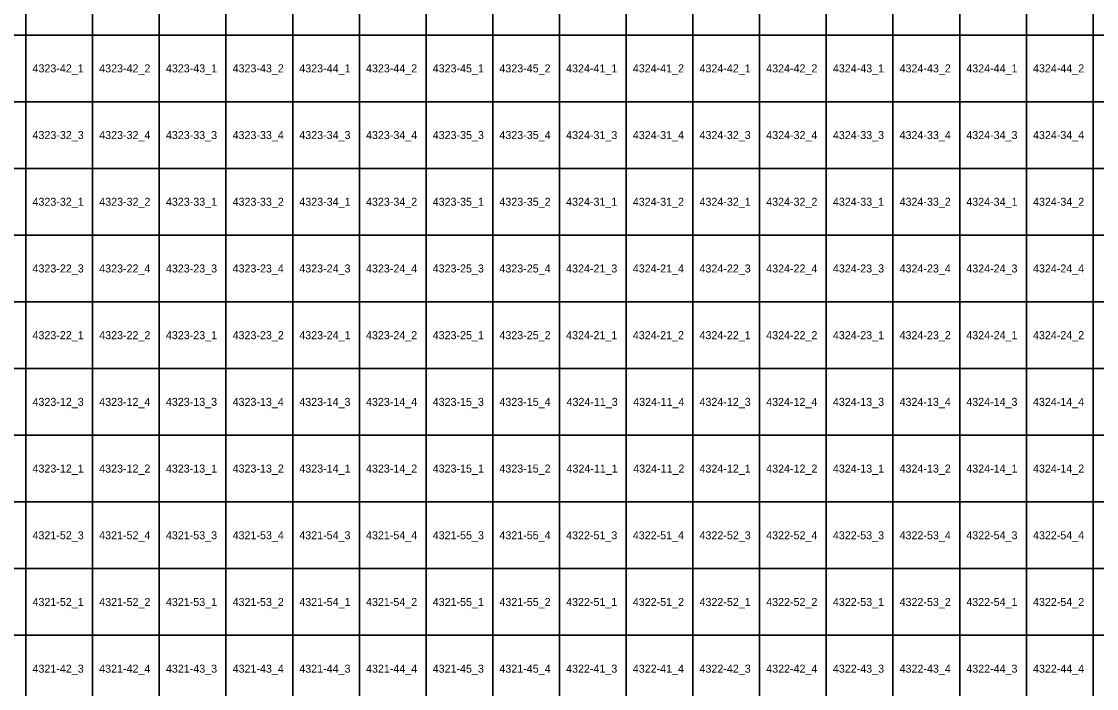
# Model space of a CAD drawing. Extents: x 312500 to 765000, y 172500 to 440000.
# Drawn here: x 554835 to 595129, y 318007 to 343007 of the extents above; entities that cross this region are included whole.
import ezdxf

# ---------------------------------------------------------------- set-up
doc = ezdxf.new("R2010")
doc.units = 0
doc.layers.add('Topo5_ramis_TKS2025', color=7, linetype='Continuous')
doc.layers.add('Topo5_ramis_TKS2025_Nr', color=7, linetype='Continuous')

msp = doc.modelspace()

# ---------------------------------------------------------------- linework, layer by layer
at = {"layer": 'Topo5_ramis_TKS2025'}
for points in [[(552500, 342500), (552500, 345000), (555000, 345000), (555000, 342500), (552500, 342500)], [(555000, 342500), (555000, 345000), (557500, 345000), (557500, 342500), (555000, 342500)], [(557500, 342500), (557500, 345000), (560000, 345000), (560000, 342500), (557500, 342500)], [(560000, 342500), (560000, 345000), (562500, 345000), (562500, 342500), (560000, 342500)], [(562500, 342500), (562500, 345000), (565000, 345000), (565000, 342500), (562500, 342500)], [(565000, 342500), (565000, 345000), (567500, 345000), (567500, 342500), (565000, 342500)], [(567500, 342500), (567500, 345000), (570000, 345000), (570000, 342500), (567500, 342500)], [(570000, 342500), (570000, 345000), (572500, 345000), (572500, 342500), (570000, 342500)], [(572500, 342500), (572500, 345000), (575000, 345000), (575000, 342500), (572500, 342500)], [(575000, 342500), (575000, 345000), (577500, 345000), (577500, 342500), (575000, 342500)], [(577500, 342500), (577500, 345000), (580000, 345000), (580000, 342500), (577500, 342500)], [(580000, 342500), (580000, 345000), (582500, 345000), (582500, 342500), (580000, 342500)], [(582500, 342500), (582500, 345000), (585000, 345000), (585000, 342500), (582500, 342500)], [(585000, 342500), (585000, 345000), (587500, 345000), (587500, 342500), (585000, 342500)], [(587500, 342500), (587500, 345000), (590000, 345000), (590000, 342500), (587500, 342500)], [(590000, 342500), (590000, 345000), (592500, 345000), (592500, 342500), (590000, 342500)], [(592500, 342500), (592500, 345000), (595000, 345000), (595000, 342500), (592500, 342500)], [(595000, 342500), (595000, 345000), (597500, 345000), (597500, 342500), (595000, 342500)], [(552500, 340000), (552500, 342500), (555000, 342500), (555000, 340000), (552500, 340000)], [(555000, 340000), (555000, 342500), (557500, 342500), (557500, 340000), (555000, 340000)], [(557500, 340000), (557500, 342500), (560000, 342500), (560000, 340000), (557500, 340000)], [(560000, 340000), (560000, 342500), (562500, 342500), (562500, 340000), (560000, 340000)], [(562500, 340000), (562500, 342500), (565000, 342500), (565000, 340000), (562500, 340000)], [(565000, 340000), (565000, 342500), (567500, 342500), (567500, 340000), (565000, 340000)], [(567500, 340000), (567500, 342500), (570000, 342500), (570000, 340000), (567500, 340000)], [(570000, 340000), (570000, 342500), (572500, 342500), (572500, 340000), (570000, 340000)], [(572500, 340000), (572500, 342500), (575000, 342500), (575000, 340000), (572500, 340000)], [(575000, 340000), (575000, 342500), (577500, 342500), (577500, 340000), (575000, 340000)], [(577500, 340000), (577500, 342500), (580000, 342500), (580000, 340000), (577500, 340000)], [(580000, 340000), (580000, 342500), (582500, 342500), (582500, 340000), (580000, 340000)], [(582500, 340000), (582500, 342500), (585000, 342500), (585000, 340000), (582500, 340000)], [(585000, 340000), (585000, 342500), (587500, 342500), (587500, 340000), (585000, 340000)], [(587500, 340000), (587500, 342500), (590000, 342500), (590000, 340000), (587500, 340000)], [(590000, 340000), (590000, 342500), (592500, 342500), (592500, 340000), (590000, 340000)], [(592500, 340000), (592500, 342500), (595000, 342500), (595000, 340000), (592500, 340000)], [(595000, 340000), (595000, 342500), (597500, 342500), (597500, 340000), (595000, 340000)], [(552500, 337500), (552500, 340000), (555000, 340000), (555000, 337500), (552500, 337500)], [(555000, 337500), (555000, 340000), (557500, 340000), (557500, 337500), (555000, 337500)], [(557500, 337500), (557500, 340000), (560000, 340000), (560000, 337500), (557500, 337500)], [(560000, 337500), (560000, 340000), (562500, 340000), (562500, 337500), (560000, 337500)], [(562500, 337500), (562500, 340000), (565000, 340000), (565000, 337500), (562500, 337500)], [(565000, 337500), (565000, 340000), (567500, 340000), (567500, 337500), (565000, 337500)], [(567500, 337500), (567500, 340000), (570000, 340000), (570000, 337500), (567500, 337500)], [(570000, 337500), (570000, 340000), (572500, 340000), (572500, 337500), (570000, 337500)], [(572500, 337500), (572500, 340000), (575000, 340000), (575000, 337500), (572500, 337500)], [(575000, 337500), (575000, 340000), (577500, 340000), (577500, 337500), (575000, 337500)], [(577500, 337500), (577500, 340000), (580000, 340000), (580000, 337500), (577500, 337500)], [(580000, 337500), (580000, 340000), (582500, 340000), (582500, 337500), (580000, 337500)], [(582500, 337500), (582500, 340000), (585000, 340000), (585000, 337500), (582500, 337500)], [(585000, 337500), (585000, 340000), (587500, 340000), (587500, 337500), (585000, 337500)], [(587500, 337500), (587500, 340000), (590000, 340000), (590000, 337500), (587500, 337500)], [(590000, 337500), (590000, 340000), (592500, 340000), (592500, 337500), (590000, 337500)], [(592500, 337500), (592500, 340000), (595000, 340000), (595000, 337500), (592500, 337500)], [(595000, 337500), (595000, 340000), (597500, 340000), (597500, 337500), (595000, 337500)], [(552500, 335000), (552500, 337500), (555000, 337500), (555000, 335000), (552500, 335000)], [(555000, 335000), (555000, 337500), (557500, 337500), (557500, 335000), (555000, 335000)], [(557500, 335000), (557500, 337500), (560000, 337500), (560000, 335000), (557500, 335000)], [(560000, 335000), (560000, 337500), (562500, 337500), (562500, 335000), (560000, 335000)], [(562500, 335000), (562500, 337500), (565000, 337500), (565000, 335000), (562500, 335000)], [(565000, 335000), (565000, 337500), (567500, 337500), (567500, 335000), (565000, 335000)], [(567500, 335000), (567500, 337500), (570000, 337500), (570000, 335000), (567500, 335000)], [(570000, 335000), (570000, 337500), (572500, 337500), (572500, 335000), (570000, 335000)], [(572500, 335000), (572500, 337500), (575000, 337500), (575000, 335000), (572500, 335000)], [(575000, 335000), (575000, 337500), (577500, 337500), (577500, 335000), (575000, 335000)], [(577500, 335000), (577500, 337500), (580000, 337500), (580000, 335000), (577500, 335000)], [(580000, 335000), (580000, 337500), (582500, 337500), (582500, 335000), (580000, 335000)], [(582500, 335000), (582500, 337500), (585000, 337500), (585000, 335000), (582500, 335000)], [(585000, 335000), (585000, 337500), (587500, 337500), (587500, 335000), (585000, 335000)], [(587500, 335000), (587500, 337500), (590000, 337500), (590000, 335000), (587500, 335000)], [(590000, 335000), (590000, 337500), (592500, 337500), (592500, 335000), (590000, 335000)], [(592500, 335000), (592500, 337500), (595000, 337500), (595000, 335000), (592500, 335000)], [(595000, 335000), (595000, 337500), (597500, 337500), (597500, 335000), (595000, 335000)], [(552500, 332500), (552500, 335000), (555000, 335000), (555000, 332500), (552500, 332500)], [(555000, 332500), (555000, 335000), (557500, 335000), (557500, 332500), (555000, 332500)], [(557500, 332500), (557500, 335000), (560000, 335000), (560000, 332500), (557500, 332500)], [(560000, 332500), (560000, 335000), (562500, 335000), (562500, 332500), (560000, 332500)], [(562500, 332500), (562500, 335000), (565000, 335000), (565000, 332500), (562500, 332500)], [(565000, 332500), (565000, 335000), (567500, 335000), (567500, 332500), (565000, 332500)], [(567500, 332500), (567500, 335000), (570000, 335000), (570000, 332500), (567500, 332500)], [(570000, 332500), (570000, 335000), (572500, 335000), (572500, 332500), (570000, 332500)], [(572500, 332500), (572500, 335000), (575000, 335000), (575000, 332500), (572500, 332500)], [(575000, 332500), (575000, 335000), (577500, 335000), (577500, 332500), (575000, 332500)], [(577500, 332500), (577500, 335000), (580000, 335000), (580000, 332500), (577500, 332500)], [(580000, 332500), (580000, 335000), (582500, 335000), (582500, 332500), (580000, 332500)], [(582500, 332500), (582500, 335000), (585000, 335000), (585000, 332500), (582500, 332500)], [(585000, 332500), (585000, 335000), (587500, 335000), (587500, 332500), (585000, 332500)], [(587500, 332500), (587500, 335000), (590000, 335000), (590000, 332500), (587500, 332500)], [(590000, 332500), (590000, 335000), (592500, 335000), (592500, 332500), (590000, 332500)], [(592500, 332500), (592500, 335000), (595000, 335000), (595000, 332500), (592500, 332500)], [(595000, 332500), (595000, 335000), (597500, 335000), (597500, 332500), (595000, 332500)], [(552500, 330000), (552500, 332500), (555000, 332500), (555000, 330000), (552500, 330000)], [(555000, 330000), (555000, 332500), (557500, 332500), (557500, 330000), (555000, 330000)], [(557500, 330000), (557500, 332500), (560000, 332500), (560000, 330000), (557500, 330000)], [(560000, 330000), (560000, 332500), (562500, 332500), (562500, 330000), (560000, 330000)], [(562500, 330000), (562500, 332500), (565000, 332500), (565000, 330000), (562500, 330000)], [(565000, 330000), (565000, 332500), (567500, 332500), (567500, 330000), (565000, 330000)], [(567500, 330000), (567500, 332500), (570000, 332500), (570000, 330000), (567500, 330000)], [(570000, 330000), (570000, 332500), (572500, 332500), (572500, 330000), (570000, 330000)], [(572500, 330000), (572500, 332500), (575000, 332500), (575000, 330000), (572500, 330000)], [(575000, 330000), (575000, 332500), (577500, 332500), (577500, 330000), (575000, 330000)], [(577500, 330000), (577500, 332500), (580000, 332500), (580000, 330000), (577500, 330000)], [(580000, 330000), (580000, 332500), (582500, 332500), (582500, 330000), (580000, 330000)], [(582500, 330000), (582500, 332500), (585000, 332500), (585000, 330000), (582500, 330000)], [(585000, 330000), (585000, 332500), (587500, 332500), (587500, 330000), (585000, 330000)], [(587500, 330000), (587500, 332500), (590000, 332500), (590000, 330000), (587500, 330000)], [(590000, 330000), (590000, 332500), (592500, 332500), (592500, 330000), (590000, 330000)], [(592500, 330000), (592500, 332500), (595000, 332500), (595000, 330000), (592500, 330000)], [(595000, 330000), (595000, 332500), (597500, 332500), (597500, 330000), (595000, 330000)], [(552500, 327500), (552500, 330000), (555000, 330000), (555000, 327500), (552500, 327500)], [(555000, 327500), (555000, 330000), (557500, 330000), (557500, 327500), (555000, 327500)], [(557500, 327500), (557500, 330000), (560000, 330000), (560000, 327500), (557500, 327500)], [(560000, 327500), (560000, 330000), (562500, 330000), (562500, 327500), (560000, 327500)], [(562500, 327500), (562500, 330000), (565000, 330000), (565000, 327500), (562500, 327500)], [(565000, 327500), (565000, 330000), (567500, 330000), (567500, 327500), (565000, 327500)], [(567500, 327500), (567500, 330000), (570000, 330000), (570000, 327500), (567500, 327500)], [(570000, 327500), (570000, 330000), (572500, 330000), (572500, 327500), (570000, 327500)], [(572500, 327500), (572500, 330000), (575000, 330000), (575000, 327500), (572500, 327500)], [(575000, 327500), (575000, 330000), (577500, 330000), (577500, 327500), (575000, 327500)], [(577500, 327500), (577500, 330000), (580000, 330000), (580000, 327500), (577500, 327500)], [(580000, 327500), (580000, 330000), (582500, 330000), (582500, 327500), (580000, 327500)], [(582500, 327500), (582500, 330000), (585000, 330000), (585000, 327500), (582500, 327500)], [(585000, 327500), (585000, 330000), (587500, 330000), (587500, 327500), (585000, 327500)], [(587500, 327500), (587500, 330000), (590000, 330000), (590000, 327500), (587500, 327500)], [(590000, 327500), (590000, 330000), (592500, 330000), (592500, 327500), (590000, 327500)], [(592500, 327500), (592500, 330000), (595000, 330000), (595000, 327500), (592500, 327500)], [(595000, 327500), (595000, 330000), (597500, 330000), (597500, 327500), (595000, 327500)], [(552500, 325000), (552500, 327500), (555000, 327500), (555000, 325000), (552500, 325000)], [(555000, 325000), (555000, 327500), (557500, 327500), (557500, 325000), (555000, 325000)], [(557500, 325000), (557500, 327500), (560000, 327500), (560000, 325000), (557500, 325000)], [(560000, 325000), (560000, 327500), (562500, 327500), (562500, 325000), (560000, 325000)], [(562500, 325000), (562500, 327500), (565000, 327500), (565000, 325000), (562500, 325000)], [(565000, 325000), (565000, 327500), (567500, 327500), (567500, 325000), (565000, 325000)], [(567500, 325000), (567500, 327500), (570000, 327500), (570000, 325000), (567500, 325000)], [(570000, 325000), (570000, 327500), (572500, 327500), (572500, 325000), (570000, 325000)], [(572500, 325000), (572500, 327500), (575000, 327500), (575000, 325000), (572500, 325000)], [(575000, 325000), (575000, 327500), (577500, 327500), (577500, 325000), (575000, 325000)], [(577500, 325000), (577500, 327500), (580000, 327500), (580000, 325000), (577500, 325000)], [(580000, 325000), (580000, 327500), (582500, 327500), (582500, 325000), (580000, 325000)], [(582500, 325000), (582500, 327500), (585000, 327500), (585000, 325000), (582500, 325000)], [(585000, 325000), (585000, 327500), (587500, 327500), (587500, 325000), (585000, 325000)], [(587500, 325000), (587500, 327500), (590000, 327500), (590000, 325000), (587500, 325000)], [(590000, 325000), (590000, 327500), (592500, 327500), (592500, 325000), (590000, 325000)], [(592500, 325000), (592500, 327500), (595000, 327500), (595000, 325000), (592500, 325000)], [(595000, 325000), (595000, 327500), (597500, 327500), (597500, 325000), (595000, 325000)], [(552500, 322500), (552500, 325000), (555000, 325000), (555000, 322500), (552500, 322500)], [(555000, 322500), (555000, 325000), (557500, 325000), (557500, 322500), (555000, 322500)], [(557500, 322500), (557500, 325000), (560000, 325000), (560000, 322500), (557500, 322500)], [(560000, 322500), (560000, 325000), (562500, 325000), (562500, 322500), (560000, 322500)], [(562500, 322500), (562500, 325000), (565000, 325000), (565000, 322500), (562500, 322500)], [(565000, 322500), (565000, 325000), (567500, 325000), (567500, 322500), (565000, 322500)], [(567500, 322500), (567500, 325000), (570000, 325000), (570000, 322500), (567500, 322500)], [(570000, 322500), (570000, 325000), (572500, 325000), (572500, 322500), (570000, 322500)], [(572500, 322500), (572500, 325000), (575000, 325000), (575000, 322500), (572500, 322500)], [(575000, 322500), (575000, 325000), (577500, 325000), (577500, 322500), (575000, 322500)], [(577500, 322500), (577500, 325000), (580000, 325000), (580000, 322500), (577500, 322500)], [(580000, 322500), (580000, 325000), (582500, 325000), (582500, 322500), (580000, 322500)], [(582500, 322500), (582500, 325000), (585000, 325000), (585000, 322500), (582500, 322500)], [(585000, 322500), (585000, 325000), (587500, 325000), (587500, 322500), (585000, 322500)], [(587500, 322500), (587500, 325000), (590000, 325000), (590000, 322500), (587500, 322500)], [(590000, 322500), (590000, 325000), (592500, 325000), (592500, 322500), (590000, 322500)], [(592500, 322500), (592500, 325000), (595000, 325000), (595000, 322500), (592500, 322500)], [(595000, 322500), (595000, 325000), (597500, 325000), (597500, 322500), (595000, 322500)], [(552500, 320000), (552500, 322500), (555000, 322500), (555000, 320000), (552500, 320000)], [(555000, 320000), (555000, 322500), (557500, 322500), (557500, 320000), (555000, 320000)], [(557500, 320000), (557500, 322500), (560000, 322500), (560000, 320000), (557500, 320000)], [(560000, 320000), (560000, 322500), (562500, 322500), (562500, 320000), (560000, 320000)], [(562500, 320000), (562500, 322500), (565000, 322500), (565000, 320000), (562500, 320000)], [(565000, 320000), (565000, 322500), (567500, 322500), (567500, 320000), (565000, 320000)], [(567500, 320000), (567500, 322500), (570000, 322500), (570000, 320000), (567500, 320000)], [(570000, 320000), (570000, 322500), (572500, 322500), (572500, 320000), (570000, 320000)], [(572500, 320000), (572500, 322500), (575000, 322500), (575000, 320000), (572500, 320000)], [(575000, 320000), (575000, 322500), (577500, 322500), (577500, 320000), (575000, 320000)], [(577500, 320000), (577500, 322500), (580000, 322500), (580000, 320000), (577500, 320000)], [(580000, 320000), (580000, 322500), (582500, 322500), (582500, 320000), (580000, 320000)], [(582500, 320000), (582500, 322500), (585000, 322500), (585000, 320000), (582500, 320000)], [(585000, 320000), (585000, 322500), (587500, 322500), (587500, 320000), (585000, 320000)], [(587500, 320000), (587500, 322500), (590000, 322500), (590000, 320000), (587500, 320000)], [(590000, 320000), (590000, 322500), (592500, 322500), (592500, 320000), (590000, 320000)], [(592500, 320000), (592500, 322500), (595000, 322500), (595000, 320000), (592500, 320000)], [(595000, 320000), (595000, 322500), (597500, 322500), (597500, 320000), (595000, 320000)], [(552500, 317500), (552500, 320000), (555000, 320000), (555000, 317500), (552500, 317500)], [(555000, 317500), (555000, 320000), (557500, 320000), (557500, 317500), (555000, 317500)], [(557500, 317500), (557500, 320000), (560000, 320000), (560000, 317500), (557500, 317500)], [(560000, 317500), (560000, 320000), (562500, 320000), (562500, 317500), (560000, 317500)], [(562500, 317500), (562500, 320000), (565000, 320000), (565000, 317500), (562500, 317500)], [(565000, 317500), (565000, 320000), (567500, 320000), (567500, 317500), (565000, 317500)], [(567500, 317500), (567500, 320000), (570000, 320000), (570000, 317500), (567500, 317500)], [(570000, 317500), (570000, 320000), (572500, 320000), (572500, 317500), (570000, 317500)], [(572500, 317500), (572500, 320000), (575000, 320000), (575000, 317500), (572500, 317500)], [(575000, 317500), (575000, 320000), (577500, 320000), (577500, 317500), (575000, 317500)], [(577500, 317500), (577500, 320000), (580000, 320000), (580000, 317500), (577500, 317500)], [(580000, 317500), (580000, 320000), (582500, 320000), (582500, 317500), (580000, 317500)], [(582500, 317500), (582500, 320000), (585000, 320000), (585000, 317500), (582500, 317500)], [(585000, 317500), (585000, 320000), (587500, 320000), (587500, 317500), (585000, 317500)], [(587500, 317500), (587500, 320000), (590000, 320000), (590000, 317500), (587500, 317500)], [(590000, 317500), (590000, 320000), (592500, 320000), (592500, 317500), (590000, 317500)], [(592500, 317500), (592500, 320000), (595000, 320000), (595000, 317500), (592500, 317500)], [(595000, 317500), (595000, 320000), (597500, 320000), (597500, 317500), (595000, 317500)]]:
    msp.add_lwpolyline(points, dxfattribs=at)

# ---------------------------------------------------------------- texts
at = {"layer": 'Topo5_ramis_TKS2025_Nr'}
for s, p in [('4323-42_1', (555248, 341100)), ('4323-42_2', (557748, 341100)), ('4323-43_1', (560248, 341100)), ('4323-43_2', (562748, 341100)), ('4323-44_1', (565248, 341100)), ('4323-44_2', (567748, 341100)), ('4323-45_1', (570248, 341100)), ('4323-45_2', (572748, 341100)), ('4324-41_1', (575248, 341100)), ('4324-41_2', (577748, 341100)), ('4324-42_1', (580248, 341100)), ('4324-42_2', (582748, 341100)), ('4324-43_1', (585248, 341100)), ('4324-43_2', (587748, 341100)), ('4324-44_1', (590248, 341100)), ('4324-44_2', (592748, 341100)), ('4323-32_3', (555248, 338600)), ('4323-32_4', (557748, 338600)), ('4323-33_3', (560248, 338600)), ('4323-33_4', (562748, 338600)), ('4323-34_3', (565248, 338600)), ('4323-34_4', (567748, 338600)), ('4323-35_3', (570248, 338600)), ('4323-35_4', (572748, 338600)), ('4324-31_3', (575248, 338600)), ('4324-31_4', (577748, 338600)), ('4324-32_3', (580248, 338600)), ('4324-32_4', (582748, 338600)), ('4324-33_3', (585248, 338600)), ('4324-33_4', (587748, 338600)), ('4324-34_3', (590248, 338600)), ('4324-34_4', (592748, 338600)), ('4323-32_1', (555248, 336100)), ('4323-32_2', (557748, 336100)), ('4323-33_1', (560248, 336100)), ('4323-33_2', (562748, 336100)), ('4323-34_1', (565248, 336100)), ('4323-34_2', (567748, 336100)), ('4323-35_1', (570248, 336100)), ('4323-35_2', (572748, 336100)), ('4324-31_1', (575248, 336100)), ('4324-31_2', (577748, 336100)), ('4324-32_1', (580248, 336100)), ('4324-32_2', (582748, 336100)), ('4324-33_1', (585248, 336100)), ('4324-33_2', (587748, 336100)), ('4324-34_1', (590248, 336100)), ('4324-34_2', (592748, 336100)), ('4323-22_3', (555248, 333600)), ('4323-22_4', (557748, 333600)), ('4323-23_3', (560248, 333600)), ('4323-23_4', (562748, 333600)), ('4323-24_3', (565248, 333600)), ('4323-24_4', (567748, 333600)), ('4323-25_3', (570248, 333600)), ('4323-25_4', (572748, 333600)), ('4324-21_3', (575248, 333600)), ('4324-21_4', (577748, 333600)), ('4324-22_3', (580248, 333600)), ('4324-22_4', (582748, 333600)), ('4324-23_3', (585248, 333600)), ('4324-23_4', (587748, 333600)), ('4324-24_3', (590248, 333600)), ('4324-24_4', (592748, 333600)), ('4323-22_1', (555248, 331100)), ('4323-22_2', (557748, 331100)), ('4323-23_1', (560248, 331100)), ('4323-23_2', (562748, 331100)), ('4323-24_1', (565248, 331100)), ('4323-24_2', (567748, 331100)), ('4323-25_1', (570248, 331100)), ('4323-25_2', (572748, 331100)), ('4324-21_1', (575248, 331100)), ('4324-21_2', (577748, 331100)), ('4324-22_1', (580248, 331100)), ('4324-22_2', (582748, 331100)), ('4324-23_1', (585248, 331100)), ('4324-23_2', (587748, 331100)), ('4324-24_1', (590248, 331100)), ('4324-24_2', (592748, 331100)), ('4323-12_3', (555248, 328600)), ('4323-12_4', (557748, 328600)), ('4323-13_3', (560248, 328600)), ('4323-13_4', (562748, 328600)), ('4323-14_3', (565248, 328600)), ('4323-14_4', (567748, 328600)), ('4323-15_3', (570248, 328600)), ('4323-15_4', (572748, 328600)), ('4324-11_3', (575264, 328600)), ('4324-11_4', (577764, 328600)), ('4324-12_3', (580248, 328600)), ('4324-12_4', (582748, 328600)), ('4324-13_3', (585248, 328600)), ('4324-13_4', (587748, 328600)), ('4324-14_3', (590248, 328600)), ('4324-14_4', (592748, 328600)), ('4323-12_1', (555248, 326100)), ('4323-12_2', (557748, 326100)), ('4323-13_1', (560248, 326100)), ('4323-13_2', (562748, 326100)), ('4323-14_1', (565248, 326100)), ('4323-14_2', (567748, 326100)), ('4323-15_1', (570248, 326100)), ('4323-15_2', (572748, 326100)), ('4324-11_1', (575264, 326100)), ('4324-11_2', (577764, 326100)), ('4324-12_1', (580248, 326100)), ('4324-12_2', (582748, 326100)), ('4324-13_1', (585248, 326100)), ('4324-13_2', (587748, 326100)), ('4324-14_1', (590248, 326100)), ('4324-14_2', (592748, 326100)), ('4321-52_3', (555248, 323600)), ('4321-52_4', (557748, 323600)), ('4321-53_3', (560248, 323600)), ('4321-53_4', (562748, 323600)), ('4321-54_3', (565248, 323600)), ('4321-54_4', (567748, 323600)), ('4321-55_3', (570248, 323600)), ('4321-55_4', (572748, 323600)), ('4322-51_3', (575248, 323600)), ('4322-51_4', (577748, 323600)), ('4322-52_3', (580248, 323600)), ('4322-52_4', (582748, 323600)), ('4322-53_3', (585248, 323600)), ('4322-53_4', (587748, 323600)), ('4322-54_3', (590248, 323600)), ('4322-54_4', (592748, 323600)), ('4321-52_1', (555248, 321100)), ('4321-52_2', (557748, 321100)), ('4321-53_1', (560248, 321100)), ('4321-53_2', (562748, 321100)), ('4321-54_1', (565248, 321100)), ('4321-54_2', (567748, 321100)), ('4321-55_1', (570248, 321100)), ('4321-55_2', (572748, 321100)), ('4322-51_1', (575248, 321100)), ('4322-51_2', (577748, 321100)), ('4322-52_1', (580248, 321100)), ('4322-52_2', (582748, 321100)), ('4322-53_1', (585248, 321100)), ('4322-53_2', (587748, 321100)), ('4322-54_1', (590248, 321100)), ('4322-54_2', (592748, 321100)), ('4321-42_3', (555248, 318600)), ('4321-42_4', (557748, 318600)), ('4321-43_3', (560248, 318600)), ('4321-43_4', (562748, 318600)), ('4321-44_3', (565248, 318600)), ('4321-44_4', (567748, 318600)), ('4321-45_3', (570248, 318600)), ('4321-45_4', (572748, 318600)), ('4322-41_3', (575248, 318600)), ('4322-41_4', (577748, 318600)), ('4322-42_3', (580248, 318600)), ('4322-42_4', (582748, 318600)), ('4322-43_3', (585248, 318600)), ('4322-43_4', (587748, 318600)), ('4322-44_3', (590248, 318600)), ('4322-44_4', (592748, 318600))]:
    msp.add_text(s, height=300, dxfattribs=at).set_placement(p)

doc.saveas('drawing.dxf')
